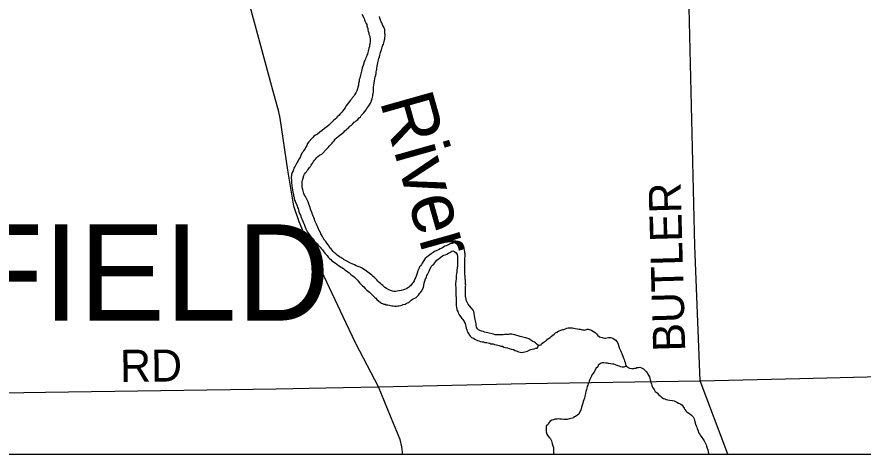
# Model space of a CAD drawing. Extents: x 0 to 34, y 0 to 22.
# Drawn here: x 5.775 to 7.272, y 14.1 to 14.874 of the extents above; entities that cross this region are included whole.
import ezdxf

# ---------------------------------------------------------------- set-up
doc = ezdxf.new("R2010")
doc.units = 0
for name, color, linetype in [('GM_X_Corporation', 7, 'Continuous'), ('GM_X_County_Road', 7, 'Continuous'), ('GM_X_County_Road_Text', 7, 'Continuous'), ('GM_X_Minor_River', 7, 'Continuous'), ('GM_X_Minor_River_Text', 7, 'Continuous'), ('GM_X_Township_Road', 7, 'Continuous'), ('GM_X_Township_Text', 7, 'Continuous')]:
    doc.layers.add(name, color=color, linetype=linetype)

msp = doc.modelspace()

# ---------------------------------------------------------------- linework, layer by layer
at = {"layer": 'GM_X_Corporation'}
msp.add_lwpolyline([(2.1, 20.2456), (2.1, 14.1), (8.0383, 14.1), (8.035, 14.2498), (8.0349, 14.2572), (8.0297, 14.4963), (8.0262, 14.6555), (8.0153, 15.2273), (7.992, 16.4534)], dxfattribs=at)
msp.add_lwpolyline([(3.6901, 15.2048), (3.5209, 15.2041), (2.7366, 15.2014), (2.7422, 14.8151), (2.7753, 14.1537), (2.7761, 14.1), (8.0383, 14.1), (8.035, 14.2498), (8.0349, 14.2572), (8.0297, 14.4963), (8.0262, 14.6555), (8.0153, 15.2273), (6.9496, 15.2134), (6.7394, 15.212), (6.1026, 15.2145), (5.9099, 15.2138), (5.9099, 15.0085), (3.6901, 15.0085)], close=True, dxfattribs=at)
at = {"layer": 'GM_X_County_Road'}
for points in [[(7.0323, 14.1), (6.9836, 14.2295), (6.974, 14.4689), (6.9636, 14.9155), (6.9586, 15.1042), (6.9571, 15.135), (6.9525, 15.1798), (6.9498, 15.2128)], [(6.9836, 14.2295), (7.1599, 14.2339), (7.5161, 14.2424), (8.0351, 14.2567)], [(4.3719, 14.1278), (4.3787, 14.1315), (4.3915, 14.1348), (4.4565, 14.1401), (4.5144, 14.1437), (4.5421, 14.1432), (4.5592, 14.1407), (4.571, 14.1369), (4.5894, 14.1297), (4.6067, 14.1224), (4.6223, 14.1196), (4.6839, 14.1382), (4.8054, 14.1766), (4.8436, 14.1889), (4.8607, 14.1933), (4.8848, 14.1961), (5.4016, 14.2029), (5.8255, 14.2097), (6.2339, 14.2154), (6.3212, 14.2172), (6.4144, 14.2189), (6.6754, 14.2251), (6.9836, 14.2295)]]:
    msp.add_lwpolyline(points, dxfattribs=at)
at = {"layer": 'GM_X_Minor_River'}
for points in [[(6.2998, 14.6182), (6.3014, 14.6204), (6.3037, 14.6227), (6.3056, 14.6254), (6.3075, 14.6272), (6.3105, 14.6291), (6.3144, 14.6314), (6.3224, 14.6397), (6.3255, 14.6427), (6.3278, 14.6457), (6.3301, 14.648), (6.3324, 14.6503), (6.3339, 14.6525), (6.3362, 14.6548), (6.3381, 14.6575), (6.34, 14.6594), (6.3435, 14.6624), (6.3462, 14.6646), (6.3485, 14.6665), (6.3511, 14.6684), (6.3534, 14.6703), (6.3553, 14.6722), (6.3576, 14.6741), (6.3599, 14.6763), (6.3622, 14.6786), (6.3641, 14.6805), (6.3661, 14.682), (6.3687, 14.6843), (6.3718, 14.6877), (6.3737, 14.6892), (6.3756, 14.6907), (6.3779, 14.6926), (6.3806, 14.6956), (6.3825, 14.6975), (6.3841, 14.6994), (6.3856, 14.7013), (6.3879, 14.7035), (6.3906, 14.7069), (6.3925, 14.7096), (6.394, 14.7119), (6.3959, 14.7145), (6.3975, 14.7168), (6.3986, 14.7187), (6.4005, 14.7213), (6.4017, 14.7243), (6.4025, 14.7262), (6.4036, 14.7293), (6.404, 14.7323), (6.4048, 14.7342), (6.4048, 14.7365), (6.4052, 14.7384), (6.4056, 14.7411), (6.4056, 14.7433), (6.406, 14.7498), (6.4064, 14.7532), (6.4068, 14.7566), (6.4076, 14.7612), (6.4084, 14.7646), (6.4088, 14.768), (6.4096, 14.7711), (6.4103, 14.7741), (6.4107, 14.7768), (6.4111, 14.779), (6.4115, 14.7809), (6.4119, 14.7836), (6.4123, 14.787), (6.4127, 14.7897), (6.4135, 14.7927), (6.4139, 14.7958), (6.4147, 14.798), (6.4154, 14.8007), (6.4162, 14.8037), (6.417, 14.8064), (6.4178, 14.8087), (6.4182, 14.8109), (6.4189, 14.8132), (6.4197, 14.8159), (6.4205, 14.8182), (6.4213, 14.8208), (6.4224, 14.8242), (6.4236, 14.8261), (6.4243, 14.828), (6.4247, 14.8307), (6.4255, 14.8337), (6.4259, 14.8356), (6.4259, 14.8375), (6.4263, 14.8398), (6.4263, 14.8421), (6.426, 14.8459), (6.426, 14.8485), (6.4256, 14.8516), (6.4249, 14.8543), (6.4237, 14.8573), (6.4218, 14.8604), (6.4203, 14.8634), (6.4192, 14.8657), (6.4177, 14.8703), (6.417, 14.8722), (6.4162, 14.8749)], [(6.3854, 14.8792), (6.388, 14.8735), (6.3891, 14.8716), (6.3899, 14.8689), (6.3906, 14.867)], [(6.3906, 14.867), (6.3918, 14.8647), (6.3929, 14.8625), (6.3937, 14.8606), (6.394, 14.8586), (6.3948, 14.8564), (6.3955, 14.8537), (6.3959, 14.8514), (6.3966, 14.8487), (6.3974, 14.8457), (6.3978, 14.8438), (6.3989, 14.8411), (6.3993, 14.8381), (6.3996, 14.8354), (6.3996, 14.8335), (6.3996, 14.8309), (6.3992, 14.8259), (6.3988, 14.824), (6.3984, 14.8217), (6.3976, 14.8187), (6.3969, 14.8164), (6.3965, 14.8138), (6.3957, 14.8111), (6.3949, 14.8084), (6.3938, 14.8062), (6.3934, 14.8039), (6.3922, 14.8016), (6.3914, 14.7993), (6.3903, 14.7971), (6.3895, 14.7952), (6.3887, 14.7925), (6.3876, 14.788), (6.386, 14.7838), (6.3849, 14.7807), (6.3825, 14.7713), (6.3814, 14.7659), (6.3806, 14.7633), (6.3802, 14.7602), (6.3794, 14.7564), (6.379, 14.7534), (6.3782, 14.7496), (6.3774, 14.747), (6.3763, 14.7435), (6.3747, 14.7397), (6.3732, 14.7379), (6.3721, 14.736), (6.3709, 14.7337), (6.3682, 14.7307), (6.3671, 14.7288), (6.3651, 14.7265), (6.3636, 14.7246), (6.3609, 14.7212), (6.3594, 14.7189), (6.3571, 14.7163), (6.3556, 14.7132), (6.3533, 14.7102), (6.3517, 14.7076), (6.3498, 14.7053), (6.3471, 14.7023), (6.3444, 14.6993), (6.3418, 14.697), (6.3406, 14.6951), (6.3379, 14.6932), (6.3352, 14.6909), (6.333, 14.6887), (6.3303, 14.686), (6.3268, 14.6823), (6.323, 14.6796), (6.3192, 14.6766), (6.315, 14.6732), (6.3108, 14.6698), (6.3066, 14.6668), (6.3031, 14.6649), (6.3004, 14.663), (6.2989, 14.6612), (6.297, 14.6593), (6.2916, 14.6532), (6.2893, 14.6498), (6.2878, 14.6464), (6.2859, 14.6434), (6.2847, 14.6411), (6.2836, 14.6392), (6.282, 14.6373), (6.2805, 14.6347), (6.2789, 14.6328), (6.2774, 14.629), (6.2759, 14.6252), (6.2739, 14.6221), (6.272, 14.6184), (6.2701, 14.6157), (6.2674, 14.6096), (6.2655, 14.6074), (6.2639, 14.6013), (6.262, 14.5986), (6.2612, 14.5968), (6.2608, 14.5949), (6.2605, 14.593), (6.2604, 14.5903), (6.2604, 14.5884), (6.2608, 14.5853), (6.2608, 14.5831)], [(6.4449, 14.3879), (6.4418, 14.3879), (6.4396, 14.3883), (6.4377, 14.3891), (6.4331, 14.3906), (6.4285, 14.3933), (6.4259, 14.3949), (6.424, 14.3968), (6.4221, 14.3987), (6.4202, 14.4002), (6.4183, 14.4021), (6.416, 14.404), (6.4137, 14.406), (6.4119, 14.4083), (6.41, 14.4106), (6.4077, 14.4125), (6.4054, 14.4144), (6.4028, 14.4167), (6.3959, 14.4221), (6.3933, 14.424), (6.391, 14.4259), (6.3883, 14.4274), (6.3857, 14.4294), (6.3823, 14.4309), (6.3788, 14.4321), (6.375, 14.4336), (6.372, 14.4351), (6.3678, 14.4367), (6.3648, 14.4382), (6.3617, 14.4398), (6.3595, 14.4413), (6.3572, 14.4425), (6.3541, 14.444), (6.3519, 14.4456), (6.3496, 14.4467), (6.3477, 14.4482), (6.3458, 14.4494), (6.3435, 14.4509), (6.3416, 14.4525), (6.3393, 14.4544), (6.3374, 14.4559), (6.3344, 14.459), (6.3325, 14.4609), (6.3306, 14.4632), (6.3287, 14.4655), (6.3272, 14.4682), (6.3253, 14.4708), (6.3231, 14.4735), (6.3212, 14.4766), (6.3189, 14.4789), (6.317, 14.4827), (6.3155, 14.4853), (6.314, 14.488), (6.3129, 14.4903), (6.3114, 14.4934), (6.3098, 14.496), (6.3087, 14.4991), (6.3076, 14.5017), (6.3061, 14.5044), (6.305, 14.5071), (6.3038, 14.5094), (6.3023, 14.5128), (6.3012, 14.5159), (6.3001, 14.5189), (6.2989, 14.5216), (6.2978, 14.5243), (6.2971, 14.5269), (6.2944, 14.5338), (6.2937, 14.5364), (6.2926, 14.5399), (6.2914, 14.5425), (6.2903, 14.5464), (6.2892, 14.549), (6.288, 14.5517), (6.2865, 14.554), (6.2854, 14.5563), (6.2839, 14.5586), (6.2828, 14.5612), (6.282, 14.5639), (6.2813, 14.5662), (6.2805, 14.5685), (6.2801, 14.5704), (6.2798, 14.5734), (6.2798, 14.5753), (6.2794, 14.578), (6.2798, 14.5803), (6.2798, 14.5822), (6.2802, 14.5848), (6.2806, 14.5871), (6.2826, 14.5936), (6.2837, 14.5955), (6.2856, 14.5981), (6.2872, 14.6), (6.2887, 14.6019), (6.2902, 14.6042), (6.2925, 14.6072), (6.2941, 14.6095), (6.2956, 14.6114), (6.2968, 14.6136), (6.2983, 14.6155), (6.2998, 14.6182)], [(6.2608, 14.5831), (6.2608, 14.5793), (6.2611, 14.5766), (6.2615, 14.5743), (6.2619, 14.572), (6.2626, 14.5671), (6.2633, 14.564), (6.2637, 14.5621), (6.2641, 14.5598), (6.2645, 14.5576), (6.2652, 14.5549), (6.2656, 14.5526), (6.2663, 14.5499), (6.2671, 14.548), (6.2678, 14.5457), (6.269, 14.5435), (6.2701, 14.5408), (6.2708, 14.5389), (6.2716, 14.5366), (6.2723, 14.5347), (6.2731, 14.5324), (6.2738, 14.5294), (6.275, 14.5263), (6.2765, 14.5229), (6.2776, 14.5191), (6.2791, 14.5164), (6.2802, 14.5137), (6.2814, 14.5107), (6.2829, 14.5072), (6.2836, 14.5053), (6.2847, 14.5019), (6.2862, 14.4989), (6.2877, 14.4954), (6.2889, 14.4931), (6.2908, 14.4905), (6.2923, 14.4882), (6.2938, 14.4862), (6.2953, 14.4843), (6.2976, 14.4824), (6.2995, 14.4805), (6.3017, 14.4771), (6.3044, 14.474), (6.3059, 14.4721), (6.3078, 14.4702), (6.3116, 14.4664), (6.3135, 14.4641), (6.3154, 14.4618), (6.3169, 14.4599), (6.3199, 14.456), (6.3218, 14.4537), (6.3237, 14.4514), (6.3256, 14.4488), (6.3279, 14.4465), (6.3301, 14.4446), (6.332, 14.4423), (6.3351, 14.4407), (6.3377, 14.4384), (6.3408, 14.4365), (6.3438, 14.4342), (6.3468, 14.4323), (6.3499, 14.4304), (6.3525, 14.4284), (6.3548, 14.4265), (6.3578, 14.4246), (6.3601, 14.4227), (6.3628, 14.4208), (6.3662, 14.4177), (6.3692, 14.4154), (6.3719, 14.4131), (6.3745, 14.4108), (6.3772, 14.4081), (6.3795, 14.4054), (6.3817, 14.4028), (6.384, 14.4005), (6.3863, 14.3982), (6.3889, 14.3959), (6.3912, 14.3932), (6.3939, 14.3901), (6.3965, 14.3882), (6.3984, 14.3867), (6.4003, 14.3848), (6.4022, 14.3832), (6.4041, 14.3813), (6.406, 14.3794), (6.4079, 14.3775), (6.4098, 14.376), (6.4117, 14.3737), (6.4181, 14.3683), (6.42, 14.3671), (6.4219, 14.3664), (6.4238, 14.3656), (6.4265, 14.3652), (6.4284, 14.3644), (6.4311, 14.364), (6.4333, 14.3636), (6.4356, 14.3632), (6.4383, 14.3628), (6.4406, 14.3624), (6.4432, 14.362), (6.4463, 14.362), (6.4486, 14.3624)], [(6.595, 14.3184), (6.5916, 14.32), (6.5897, 14.3219), (6.5882, 14.3246), (6.5874, 14.328), (6.5871, 14.3306), (6.5867, 14.3333), (6.5863, 14.336), (6.5856, 14.3386), (6.5852, 14.3417), (6.5845, 14.3451), (6.5837, 14.3493), (6.583, 14.3523), (6.5819, 14.3546), (6.5792, 14.3585), (6.5758, 14.3623), (6.5731, 14.3657), (6.5713, 14.3692), (6.5698, 14.3726), (6.5694, 14.3745), (6.569, 14.3772), (6.5686, 14.3791), (6.5687, 14.381), (6.5683, 14.3829), (6.5683, 14.3848), (6.5683, 14.3871), (6.5683, 14.389), (6.5687, 14.3924), (6.5687, 14.3954), (6.5687, 14.3973), (6.5688, 14.3992), (6.5684, 14.4011), (6.5684, 14.4038), (6.5677, 14.4152), (6.5673, 14.4182), (6.5673, 14.422), (6.567, 14.4258), (6.567, 14.4296), (6.567, 14.4335), (6.567, 14.4369), (6.5671, 14.4407), (6.5675, 14.4437), (6.5675, 14.4464), (6.5679, 14.4509), (6.5679, 14.4544), (6.5675, 14.4566), (6.5672, 14.4589), (6.5668, 14.4612), (6.566, 14.4639), (6.5649, 14.4666), (6.5623, 14.4704), (6.56, 14.473), (6.557, 14.4742), (6.5543, 14.475), (6.5524, 14.475), (6.5493, 14.4743), (6.5471, 14.4739), (6.5448, 14.4732), (6.5425, 14.4728), (6.5402, 14.4717), (6.5383, 14.4705), (6.5364, 14.4698), (6.5345, 14.469), (6.5322, 14.4679), (6.5295, 14.4664), (6.5268, 14.4649), (6.5238, 14.4634), (6.5207, 14.4619), (6.5176, 14.4604), (6.5138, 14.4589), (6.5115, 14.457), (6.5096, 14.4555), (6.5077, 14.4544), (6.5054, 14.4529), (6.5031, 14.451), (6.4974, 14.4461), (6.4947, 14.4427), (6.4932, 14.44), (6.4916, 14.4378), (6.4905, 14.4359), (6.4889, 14.4336), (6.4874, 14.4313), (6.4859, 14.4283), (6.4843, 14.4245), (6.4832, 14.4203), (6.4816, 14.4169), (6.4804, 14.4131), (6.4789, 14.4101), (6.4774, 14.4067), (6.4758, 14.404), (6.4743, 14.4021), (6.4712, 14.398), (6.4693, 14.3965), (6.4674, 14.395), (6.4647, 14.3931), (6.4621, 14.392), (6.459, 14.3908), (6.4544, 14.3897), (6.451, 14.389), (6.4479, 14.3882), (6.4449, 14.3879)], [(6.4486, 14.3624), (6.4512, 14.3627), (6.4535, 14.3631), (6.4558, 14.3639), (6.4585, 14.365), (6.4615, 14.3657), (6.4638, 14.3668), (6.4661, 14.3676), (6.4684, 14.3687), (6.4726, 14.3725), (6.4761, 14.3747), (6.4787, 14.3762), (6.481, 14.3774), (6.4837, 14.3796), (6.4852, 14.3815), (6.4872, 14.3842), (6.4891, 14.3864), (6.4906, 14.3883), (6.4929, 14.3925), (6.4941, 14.3955), (6.4948, 14.3986), (6.4956, 14.4024), (6.4968, 14.4069), (6.498, 14.4103), (6.4987, 14.4122), (6.4995, 14.4141), (6.4999, 14.416), (6.501, 14.4179), (6.5022, 14.4206), (6.5041, 14.424), (6.5049, 14.4259), (6.508, 14.4319), (6.5103, 14.4346), (6.5122, 14.4365), (6.5141, 14.4384), (6.5153, 14.4406), (6.5176, 14.4433), (6.5199, 14.4452), (6.5218, 14.4463), (6.5252, 14.4493), (6.5279, 14.4508), (6.5302, 14.452), (6.5325, 14.4531), (6.5355, 14.4542), (6.5382, 14.4557), (6.5405, 14.4572), (6.5424, 14.458), (6.5443, 14.4591), (6.5462, 14.4598), (6.5493, 14.4587), (6.5519, 14.4564), (6.5538, 14.4533), (6.5542, 14.4507), (6.5545, 14.4476), (6.5545, 14.4446), (6.5541, 14.4339), (6.5537, 14.4297), (6.5533, 14.4259), (6.5529, 14.4229), (6.5525, 14.4199), (6.5521, 14.4161), (6.5517, 14.4111), (6.5513, 14.4062), (6.5509, 14.402), (6.5508, 14.3986), (6.5512, 14.3952), (6.5512, 14.3921), (6.5516, 14.3898), (6.5512, 14.386), (6.5515, 14.3837), (6.5515, 14.3803), (6.5519, 14.3773), (6.5519, 14.3746), (6.5518, 14.372), (6.5518, 14.3693), (6.5518, 14.3666), (6.5522, 14.3647), (6.5522, 14.3624), (6.5525, 14.3602), (6.5533, 14.3563), (6.554, 14.3541), (6.5548, 14.3522), (6.5555, 14.3502), (6.5571, 14.3468), (6.5597, 14.3434), (6.562, 14.3403), (6.5639, 14.3384), (6.5661, 14.335), (6.5669, 14.3331), (6.5676, 14.3312), (6.5684, 14.3281), (6.5691, 14.3258), (6.5699, 14.3232), (6.5706, 14.3201), (6.5714, 14.3178), (6.5725, 14.3152), (6.577, 14.3087), (6.5793, 14.3067), (6.5824, 14.3052), (6.585, 14.3037), (6.5873, 14.3025)], [(6.6976, 14.292), (6.6992, 14.2926), (6.7023, 14.2934), (6.7027, 14.2953), (6.7073, 14.299), (6.7115, 14.3013), (6.7134, 14.3032), (6.7153, 14.3047), (6.718, 14.3066), (6.7203, 14.3088), (6.7229, 14.3107), (6.7252, 14.3126), (6.7279, 14.3145), (6.7298, 14.3156), (6.7329, 14.3175), (6.7371, 14.3197), (6.7405, 14.3205), (6.7424, 14.3209), (6.7474, 14.3227), (6.7501, 14.3235), (6.7546, 14.3238), (6.7577, 14.3234), (6.7622, 14.3226), (6.7664, 14.3218), (6.7695, 14.3214), (6.7714, 14.321), (6.7733, 14.3206), (6.7752, 14.3203), (6.7775, 14.3199), (6.7794, 14.3195), (6.7836, 14.321), (6.7855, 14.3213), (6.7874, 14.3206), (6.79, 14.3198), (6.7919, 14.319), (6.795, 14.3171), (6.7976, 14.3152), (6.7999, 14.3129), (6.8022, 14.3106), (6.8056, 14.3079), (6.8102, 14.3067), (6.8143, 14.3055), (6.8162, 14.3051), (6.8212, 14.3063), (6.825, 14.3066), (6.8288, 14.3054), (6.8315, 14.3035), (6.8341, 14.302), (6.8353, 14.3001), (6.8372, 14.2974), (6.8383, 14.2947), (6.8398, 14.2905), (6.8409, 14.2871), (6.8428, 14.2833), (6.8435, 14.2806), (6.8447, 14.278), (6.8454, 14.2761), (6.8466, 14.2734), (6.8477, 14.27), (6.8488, 14.2673), (6.8496, 14.265), (6.8507, 14.2623), (6.8514, 14.2593), (6.8522, 14.257), (6.8529, 14.2551), (6.8583, 14.252), (6.8628, 14.2516), (6.8659, 14.2516), (6.8678, 14.2519), (6.8697, 14.2523), (6.8716, 14.2531), (6.8746, 14.2534), (6.8765, 14.2538), (6.88, 14.2526), (6.8834, 14.2507), (6.8868, 14.2476), (6.8883, 14.2457), (6.8898, 14.2438), (6.891, 14.2415), (6.8928, 14.2388), (6.894, 14.2366), (6.8947, 14.2339), (6.8951, 14.2316), (6.8955, 14.2297), (6.8958, 14.2278), (6.8966, 14.2255), (6.8973, 14.2236), (6.8977, 14.2217), (6.8988, 14.2198), (6.9, 14.2175), (6.9019, 14.2144), (6.9041, 14.211), (6.9075, 14.2083), (6.9098, 14.2053), (6.9125, 14.203), (6.9159, 14.1999), (6.9185, 14.1984), (6.9208, 14.1976), (6.9235, 14.1968)], [(6.6977, 14.2919), (6.6973, 14.2923), (6.6954, 14.2938), (6.6924, 14.2969), (6.6905, 14.298), (6.6878, 14.2992), (6.6859, 14.3003), (6.684, 14.3015), (6.6821, 14.303), (6.6802, 14.3038), (6.6768, 14.3053), (6.6749, 14.3057), (6.6723, 14.3065), (6.6696, 14.3073), (6.6677, 14.3077), (6.6654, 14.3081), (6.6635, 14.3088), (6.6616, 14.3092), (6.6593, 14.31), (6.6574, 14.3104), (6.6555, 14.3112), (6.6525, 14.312), (6.6506, 14.3123), (6.6487, 14.3124), (6.6464, 14.3124), (6.6445, 14.312), (6.6418, 14.312), (6.638, 14.3117), (6.635, 14.3113), (6.6308, 14.3113), (6.627, 14.3114), (6.6239, 14.3114), (6.6209, 14.3114), (6.6178, 14.3122), (6.6079, 14.3145), (6.6049, 14.3153), (6.6022, 14.3161), (6.5999, 14.3169), (6.5969, 14.3176), (6.595, 14.3184)], [(6.5873, 14.3025), (6.5896, 14.3013), (6.5922, 14.3006), (6.5949, 14.2994), (6.5979, 14.299), (6.6002, 14.2986), (6.6029, 14.2978), (6.6059, 14.2974), (6.6086, 14.297), (6.6113, 14.2963), (6.6135, 14.2955), (6.6173, 14.2951), (6.62, 14.2943), (6.6231, 14.2935), (6.6257, 14.2927), (6.628, 14.292), (6.631, 14.2912), (6.6337, 14.2908), (6.6364, 14.2896), (6.639, 14.2888), (6.6425, 14.2881), (6.6455, 14.2869), (6.6501, 14.2857), (6.6535, 14.2849), (6.6561, 14.2834), (6.6596, 14.2822), (6.6622, 14.2811), (6.6649, 14.2803), (6.6676, 14.2799), (6.6702, 14.2803), (6.6733, 14.281), (6.6759, 14.2818), (6.6782, 14.2825), (6.6824, 14.2844), (6.6843, 14.2851), (6.6866, 14.2855), (6.6901, 14.2862), (6.6931, 14.2873), (6.6954, 14.2877), (6.6977, 14.2919)], [(6.8527, 14.2556), (6.8487, 14.254), (6.8457, 14.254), (6.8434, 14.2544), (6.84, 14.2559), (6.8369, 14.2571), (6.8335, 14.2583), (6.8305, 14.259), (6.8286, 14.2591), (6.8255, 14.2598), (6.8213, 14.2606), (6.8194, 14.261), (6.8164, 14.261), (6.813, 14.2614), (6.8107, 14.2618), (6.8084, 14.2607), (6.805, 14.2585), (6.803, 14.2577), (6.8023, 14.2547), (6.7988, 14.2516), (6.7961, 14.2448), (6.7927, 14.241), (6.7911, 14.238), (6.79, 14.2357), (6.7884, 14.2319), (6.7873, 14.2293), (6.7865, 14.227), (6.7853, 14.2244), (6.7846, 14.2221), (6.7838, 14.2202), (6.783, 14.2168), (6.7822, 14.2141), (6.7815, 14.2111), (6.7807, 14.2073), (6.7795, 14.2027), (6.7787, 14.1993), (6.7776, 14.1963), (6.7768, 14.1932), (6.776, 14.1902), (6.7749, 14.1868), (6.7737, 14.183), (6.7729, 14.1803), (6.7725, 14.1781), (6.7687, 14.1705), (6.7629, 14.1667), (6.7599, 14.166), (6.7599, 14.1641), (6.7526, 14.1622), (6.7481, 14.1611), (6.7423, 14.1611), (6.7382, 14.1616), (6.7351, 14.162), (6.7328, 14.1624), (6.7305, 14.162), (6.7283, 14.162), (6.7264, 14.1616), (6.7241, 14.1609), (6.721, 14.1598), (6.718, 14.1583), (6.7153, 14.1549), (6.7141, 14.1518), (6.7114, 14.1499), (6.711, 14.1431), (6.711, 14.1393), (6.7125, 14.1351), (6.714, 14.1324), (6.717, 14.129), (6.7189, 14.1267), (6.7204, 14.1236), (6.7212, 14.121), (6.7219, 14.1183), (6.7231, 14.1145), (6.7238, 14.1115), (6.7242, 14.1088), (6.7242, 14.1069), (6.7241, 14.1046), (6.7241, 14.102), (6.7239, 14.1)], [(6.9235, 14.1968), (6.9265, 14.196), (6.9292, 14.1956), (6.9345, 14.1948), (6.9372, 14.1941), (6.9398, 14.1933), (6.9425, 14.1917), (6.9452, 14.1902), (6.9471, 14.1894), (6.949, 14.1883), (6.9516, 14.1864), (6.9539, 14.1833), (6.9554, 14.1814), (6.9565, 14.1787), (6.9584, 14.1768), (6.9607, 14.1745), (6.9634, 14.1726), (6.9652, 14.1714), (6.9683, 14.1691), (6.9713, 14.1657), (6.9728, 14.1623), (6.9736, 14.16), (6.9743, 14.1569), (6.9754, 14.1531), (6.9762, 14.1501), (6.9773, 14.1474), (6.9781, 14.1451), (6.9799, 14.1413), (6.9807, 14.1382), (6.9822, 14.1356), (6.9837, 14.1333), (6.9852, 14.131), (6.9867, 14.1291), (6.9883, 14.1268), (6.9905, 14.1237), (6.992, 14.1211), (6.9928, 14.1188), (6.9939, 14.1165), (6.9947, 14.1138), (6.9958, 14.1104), (6.9969, 14.1077), (6.9984, 14.1009), (6.9987, 14.1)]]:
    msp.add_lwpolyline(points, dxfattribs=at)
at = {"layer": 'GM_X_Township_Road'}
for points in [[(6.3739, 14.2971), (6.3521, 14.3431), (6.2849, 14.4856), (6.2743, 14.5114), (6.2648, 14.5391), (6.2542, 14.6029), (6.2409, 14.6948), (6.2386, 14.7059), (6.2276, 14.7446), (6.1706, 14.9562), (6.1408, 15.0626), (6.1077, 15.1949), (6.1074, 15.1959)], [(6.457, 14.1), (6.4569, 14.1035), (6.4558, 14.113), (6.4531, 14.1259), (6.441, 14.1544), (6.4144, 14.2189), (6.3751, 14.2945), (6.3739, 14.2971)]]:
    msp.add_lwpolyline(points, dxfattribs=at)

# ---------------------------------------------------------------- texts
at = {"layer": 'GM_X_County_Road_Text'}
for s, rotation, p in [('BUTLER', 91.5918, (6.9572, 14.2821)), ('RD', 0.4937, (5.9577, 14.2277))]:
    msp.add_text(s, height=0.05682, rotation=rotation, dxfattribs=at).set_placement(p)
at = {"layer": 'GM_X_Minor_River_Text'}
msp.add_text('River', height=0.09474, rotation=285.7949, dxfattribs=at).set_placement((6.4164, 14.7255))
at = {"layer": 'GM_X_Township_Text'}
msp.add_text('CLARKSFIELD', height=0.170455, rotation=0, dxfattribs=at).set_placement((4.7704, 14.3364))

doc.saveas('drawing.dxf')
